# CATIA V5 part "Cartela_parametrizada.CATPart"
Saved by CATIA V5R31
Part number: Cartela_param_pilar_dintel
Material "PLA": density 1240 kg/m3, Young's modulus 3.2e+09 Pa, Poisson ratio 0.331, thermal expansion 6.84e-05 1/K
Bounding box of the stored display mesh (mm): x -3.75 to 9.35, y -3.749 to 34.731, z -2 to 2
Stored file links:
  C:\Users\super\Desktop\LEGO\TFG-2621\TFG_02621_anejos\Cartela_parametrizada.CATPart
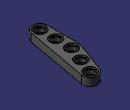
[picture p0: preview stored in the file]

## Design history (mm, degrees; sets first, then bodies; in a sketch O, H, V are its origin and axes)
Parameters
  Tipo_cartela = "dintel_dintel"
  Dist_pilares_estructura = 354.255 mm
  Long_dintel = 180 mm
  Diam_agujero = 5 mm
  N_lado_corto = 3
  Lado_cartela = 16 mm
  Espesor = 4 mm
  Angulo_cartela_pilar_dintel = 100.2497 deg {= acos((Dist_pilares_estructura/2)/Long_dintel)+90deg}
  Angulo_cartela_dintel_dintel = 159.5006 deg {= 2*(180deg-Angulo_cartela_pilar_dintel)}
  h = 10000 mm
  Altura_cartela = 10000 mm
  Angulo_cartela = 159.5006 deg
Set1 "REFERENCIAS"
  Plane1 "PLANO_CENTRAL": type OffsetPt, RefPlane XY plane of AxisSystem1, RefPoint vertex [element of Sketch1 | element of Sketch1]
  AxisSystem1: origin (0, 0, 0), X (1, 0, 0), Y (0, 1, 0), Z (0, 0, 1)
  Sketch1 "GUIA" on XY plane of AxisSystem1, origin (0, 0, 0), H (1, 0, 0), V (0, 1, 0)
    line L1 (0, 0) -> (0, 16)
    point P1 (0, 0)
    line L2 (0, 16) -> (5.6032, 30.9868)
    point P3 (5.6032, 30.9868)
    curve C1
    length L1 = 16 {= Lado_cartela}
    length L2 = 16 {= Lado_cartela}
    angle L1 L2 = 159.5006 {= Angulo_cartela}
    vertical: L1 V
    coincidence: P1 O
  Line1 "REF_LADO_LARGO": type PtPt, FirstPoint Sketch1.P3, SecondPoint vertex [YZ plane of AxisSystem1 | ZX plane of AxisSystem1 | XY plane of AxisSystem1]
  Point1 "PUNTO_MEDIO_LADO_LARGO": type OnCurve, Support Line1, Ratio 0.5
  Line2 "PERP_LADO_LARGO": type PtPt, FirstPoint vertex [element of Sketch1 | element of Sketch1], SecondPoint Point1
Body1 (main body), material "PLA"
  Sketch2 "BASE" on Plane1, origin (0, 16, 0), H (1, 0, 0), V (0, 1, 0)
    arc A1 centre (0, 0) radius 3.75 from (-3.5125, 1.3132) to (-3.75, 0) ccw
    point P1 (0, 0)
    point P2 (0, -16)
    arc A2 centre (0, -16) radius 3.75 from (-3.75, -16) to (3.6902, -16.6673) ccw
    point P3 (5.6032, 14.9868)
    arc A3 centre (5.6032, 14.9868) radius 3.75 from (9.2933, 14.3195) to (2.0906, 16.3001) ccw
    projected point E1 (5.6032, 14.9868) from Sketch1.P3
    projected point E2 (0, -16) from vertex [YZ plane of AxisSystem1 | ZX plane of AxisSystem1 | XY plane of AxisSystem1]
    line L1 (2.0906, 16.3001) -> (-3.5125, 1.3132)
    line L2 (9.2933, 14.3195) -> (3.6902, -16.6673)
    line L3 (-3.75, 0) -> (-3.75, -16)
    curve C1
    radius A3 = 3.75
    coincidence: P3 E1, P2 E2, P1 O
    tangency: L1 A3, L1 A1, L2 A3, L2 A2, L3 A1, L3 A2
    equal size: A1 A3, A3 A2
  Pad1 "CUERPO_BASE": profile Sketch2, direction (0, 0, 1), length 2 {= Espesor / 2}, mirrored extent
  Sketch3 "AGUJERO" on end face of Pad1, origin (5.4461, 13.2872, 2), H (1, 0, 0), V (0, 1, 0)
    point P1 (-5.4461, 2.7128)
    reference projected arc E1 centre (-5.4461, 2.7128) radius 3.75 from (-6.1642, 6.3934) to (-9.1961, 2.7128) ccw from edge [face of Pad1 from Sketch2.A1 | end face of Pad1]
    concentricity: E1 P1
  Hole1 "AGUJERO_CENTRAL": placed by Sketch3, at (0, 16, 2) direction (0, 0, -1), diameter 5 {= Diam_agujero}, through (limit type 3), counterbore diameter 6, counterbore depth 1
  RectPattern1 "Rep_Agujeros_Lado_1a": of Hole1, direction 1 instances 3 {= N_lado_corto}, spacing 8 {= (Lado_cartela)/(N_lado_corto -1)}, along Sketch1.L1 reversed, direction 2 instances 3 {= RectPattern1.Nb1*1}, spacing 4, along axis of face of Hole1
  RectPattern2 "Rep_Agujeros_Lado_2a": of Hole1, direction 1 instances 3 {= N_lado_corto}, spacing 8 {= Lado_cartela /(N_lado_corto -1)}, along Sketch1.L2
  RectPattern3 "Rep_Agujeros_Lado_ha": of Hole1, direction 1 instances 2, spacing 10000 {= Altura_cartela}, along Line2
  Sketch4 "AGUJERO_2" on face of RectPattern1, origin (3.4146, 13.2727, -2), H (1, 0, 0), V (0, -1, 0)
    point P1 (-3.4146, -2.7273)
    reference projected circle E1 centre (-3.4146, -2.7273) radius 2.5 from edge [face of Hole1 | face of RectPattern1]
    concentricity: E1 P1
  Hole2 "AGUJERO_CENTRAL_2": placed by Sketch4, at (0, 16, -2) direction (0, 0, 1), diameter 5, through (limit type 3), counterbore diameter 6, counterbore depth 1
  RectPattern4 "Rep_Agujeros_Lado_1b": of Hole2, direction 1 instances 3 {= N_lado_corto}, spacing 8 {= (Lado_cartela)/(N_lado_corto -1)}, along Sketch1.L1 reversed, direction 2 instances 3, spacing 4
  RectPattern5 "Rep_Agujeros_Lado_2b": of Hole2, direction 1 instances 3 {= N_lado_corto}, spacing 8 {= Lado_cartela /(N_lado_corto -1)}, along Sketch1.L2, direction 2 instances 3, spacing 4
  RectPattern6 "Rep_Agujeros_Lado_hb": of Hole2, direction 1 instances 2, spacing 10000 {= Altura_cartela}, along Line2, direction 2 instances 3, spacing 4
Relations
  h = (Lado_cartela )* (sin(90deg-((Angulo_cartela_pilar_dintel )/2))) (deactivated)
  rule "Altura_cartela":
    /*Rule created by Jesus Arozamena*/
    if h >8mm	/*= Diam_agujero*2*/
    	Altura_cartela = h
    else
    	Altura_cartela = 0mm
  rule "Angulo_cartela":
    /*Rule created by Jesus Arozamena*/
    if Tipo_cartela  == "pilar_dintel"
    	Angulo_cartela  = Angulo_cartela_pilar_dintel
    else
    	Angulo_cartela  = Angulo_cartela_dintel_dintel
  rule "Existencia_agujero_lado_largo":
    /*Rule created by Jesus Arozamena 20/12/2023*/
    if Tipo_cartela =="dintel_dintel"
    	h = 10
    else
    	h = (Lado_cartela )* (sin(90deg-((Angulo_cartela_pilar_dintel )/2)))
